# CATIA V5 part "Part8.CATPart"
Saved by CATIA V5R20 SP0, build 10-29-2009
Part number: 9CS101615
Revision: ANY
Definition: UNKNOWN
Nomenclature: 9CS101615
Source: Unknown
Bounding box of the stored display mesh (mm): x -8 to 8, y -7.5 to 7.5, z -8 to 8
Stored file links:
  C:\Users\Utente\Desktop\IO LAVORO\3D X SITO CF\CUMSA\3D files PW\pw101430\pw101430_injection\Part8.CATPart
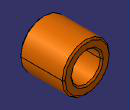
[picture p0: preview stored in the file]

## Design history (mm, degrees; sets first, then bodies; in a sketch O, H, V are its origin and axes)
Body1 "Revolución1" (main body)
  Solid1: solid without history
